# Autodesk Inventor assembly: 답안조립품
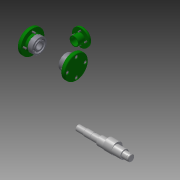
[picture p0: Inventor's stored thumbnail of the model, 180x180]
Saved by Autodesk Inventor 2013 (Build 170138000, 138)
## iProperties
Created: 2016-01
Part Number: 답안조립품
Document SubType Name: Assembly
Designer: User
Author: User
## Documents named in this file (9)
- C:\Users\User\Desktop\460126V1008\답안조립품.iam
- C:\Users\User\Desktop\460126V1008\본체.ipt
- C:\Users\User\Desktop\460126V1008\앞커버.ipt
- C:\Users\User\Desktop\460126V1008\뒤커버.ipt
- C:\Users\User\Desktop\460126V1008\볼트 M4 x 10.ipt
- C:\Users\User\Desktop\460126V1008\상부부시.ipt
- C:\Users\User\Desktop\460126V1008\볼트 M3 x 8.ipt
- C:\Users\User\Desktop\460126V1008\베어링 15 x 35 x 11.ipt
- C:\Users\User\Desktop\460126V1008\편심축.ipt
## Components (12 placed, 2 different names)
1. ISO 4762 M4 x 10:2
2. ISO 4762 M4 x 10:3
3. ISO 4762 M4 x 10:4
4. ISO 4762 M4 x 10:5
5. ISO 4762 M4 x 10:1
6. ISO 4762 M4 x 10:6
7. ISO 4762 M4 x 10:7
8. ISO 4762 M4 x 10:8
9. ISO 4762 M3 x 8:1
10. ISO 4762 M3 x 8:2
11. ISO 4762 M3 x 8:3
12. ISO 4762 M3 x 8:4
